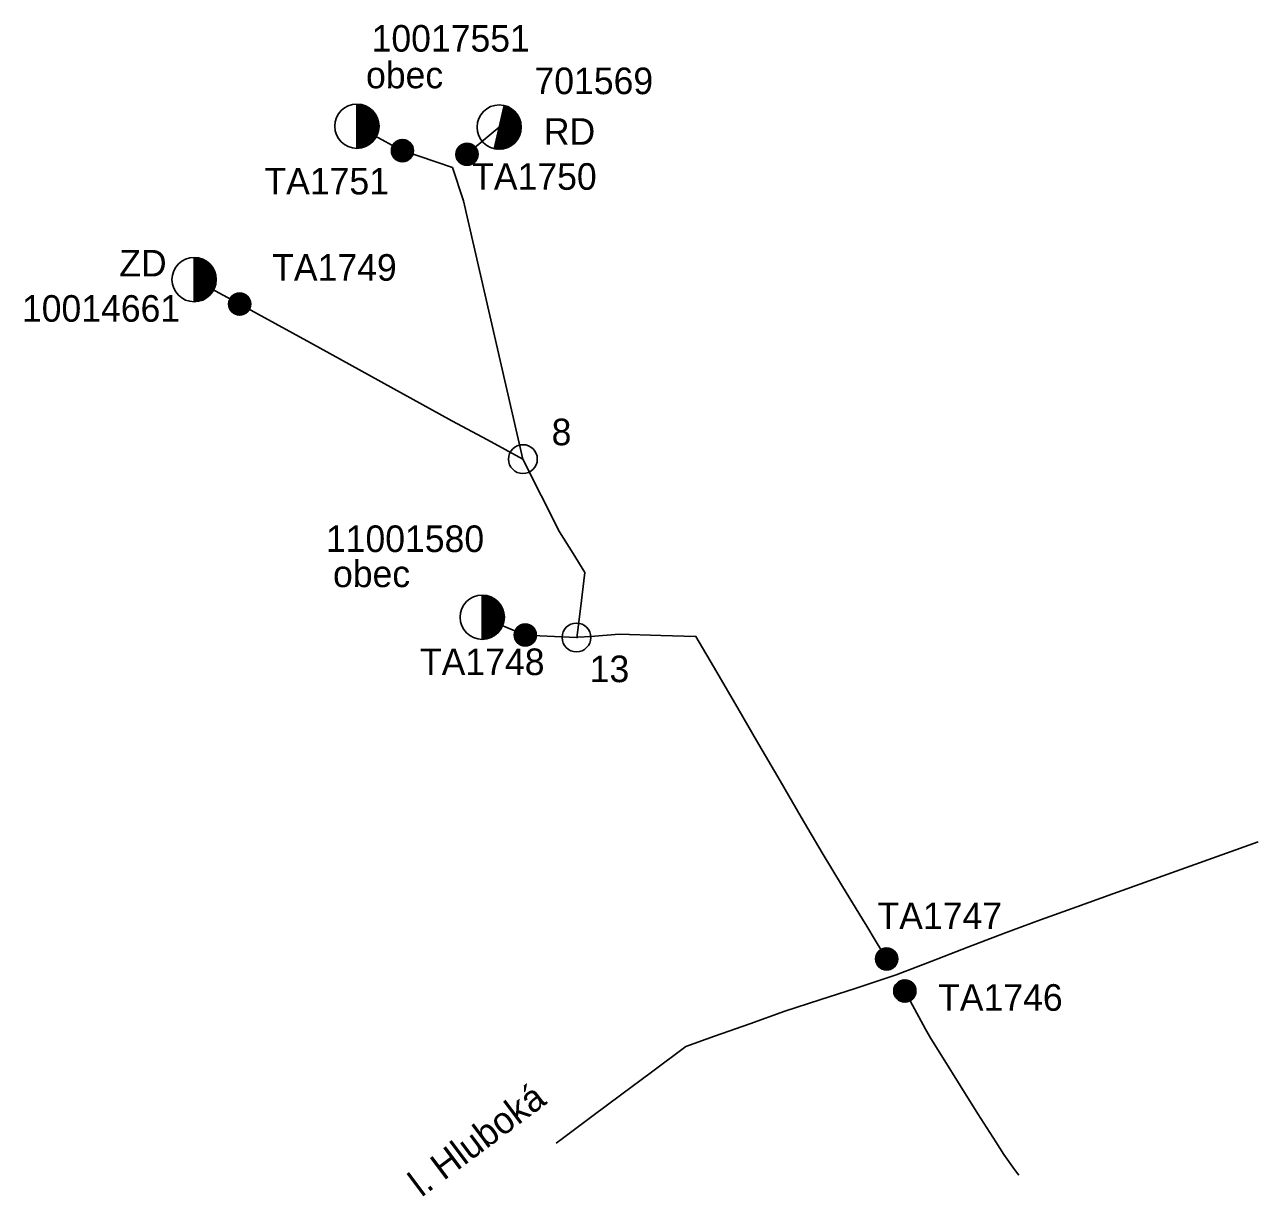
# Model space of a CAD drawing. Extents: x -749194 to -734612, y -1146817 to -1138558.
# Drawn here: x -741568 to -738789, y -1146738 to -1144095 of the extents above; entities that cross this region are included whole.
import ezdxf

# ---------------------------------------------------------------- set-up
doc = ezdxf.new("R2010")
doc.units = 0
for name, color, linetype in [('Default', 7, 'Continuous'), ('Vrstva 1', 7, 'Continuous'), ('Vrstva 2', 7, 'Continuous'), ('Vrstva 3', 7, 'Continuous'), ('Vrstva 5', 7, 'Continuous')]:
    doc.layers.add(name, color=color, linetype=linetype)

# ---------------------------------------------------------------- blocks, each defined once
blk = doc.blocks.new('PS440')
at = {"layer": 'Default'}
for p, q in [((-25, 0.1), (-0.1, 25)), ((-24.9, -1.2), (1.2, 24.9)), ((-24.9, 1.6), (-1.6, 24.9)), ((-24.8, -2.6), (2.6, 24.8)), ((-24.8, 3.2), (-3.2, 24.8)), ((-24.7, -3.8), (3.8, 24.7)), ((-24.5, -5), (5, 24.5)), ((-24.5, 4.9), (-4.9, 24.5)), ((-24.2, -6.2), (6.2, 24.2)), ((-24.1, 6.7), (-6.7, 24.1)), ((-23.9, -7.3), (7.3, 23.9)), ((-23.6, -8.3), (8.3, 23.6)), ((-23.4, 8.8), (-8.8, 23.4)), ((-23.2, -9.4), (9.4, 23.2)), ((-22.7, -10.3), (10.3, 22.7)), ((-22.3, -11.3), (11.3, 22.3)), ((-22.3, 11.3), (-11.3, 22.3)), ((-21.8, -12.2), (12.2, 21.8)), ((-21.3, -13.1), (13.1, 21.3)), ((-20.7, -14), (14, 20.7)), ((-20.1, -14.8), (14.8, 20.1)), ((-19.9, 15.2), (-15.2, 19.9)), ((-19.5, -15.6), (15.6, 19.5)), ((-18.9, -16.4), (16.4, 18.9)), ((-18.2, -17.1), (17.1, 18.2)), ((-17.5, -17.8), (17.8, 17.5)), ((-16.8, -18.5), (18.5, 16.8)), ((-16, -19.2), (19.2, 16)), ((-15.2, -19.8), (19.8, 15.2)), ((-14.4, -20.4), (20.4, 14.4)), ((-13.6, -21), (21, 13.6)), ((-12.7, -21.5), (21.5, 12.7)), ((-11.8, -22), (22, 11.8)), ((-10.8, -22.5), (22.5, 10.8)), ((-9.9, -22.9), (22.9, 9.9)), ((-8.9, -23.4), (23.4, 8.9)), ((-7.8, -23.7), (23.7, 7.8)), ((-6.7, -24.1), (24.1, 6.7)), ((-5.6, -24.3), (24.3, 5.6)), ((-4.4, -24.6), (24.6, 4.4)), ((-3.2, -24.8), (24.8, 3.2)), ((-1.9, -24.9), (24.9, 1.9)), ((-0.6, -25), (25, 0.6)), ((0.8, -25), (25, -0.8)), ((2.3, -24.9), (24.9, -2.3)), ((4, -24.7), (24.7, -4)), ((5.7, -24.3), (24.3, -5.7)), ((7.7, -23.8), (23.8, -7.7)), ((10, -22.9), (22.9, -10)), ((12.9, -21.4), (21.4, -12.9))]:
    blk.add_line(p, q, dxfattribs=at)
blk.add_circle((0, 0), 25, dxfattribs=at)
blk = doc.blocks.new('PS820')
at = {"layer": 'Vrstva 2'}
blk.add_circle((0, 0), 32.5, dxfattribs=at)
blk = doc.blocks.new('PS615')
at = {"layer": 'Default'}
for p, q in [((0, 49.1), (0.9, 50)), ((0, 46.3), (3.6, 49.9)), ((0, 47.7), (2.3, 49.9)), ((0, 44.8), (4.9, 49.8)), ((0, 43.4), (6.2, 49.6)), ((0, 42), (7.4, 49.4)), ((0, 40.6), (8.7, 49.2)), ((0, 39.2), (9.8, 49)), ((0, 37.8), (11, 48.8)), ((0, 36.4), (12.1, 48.5)), ((0, 34.9), (13.3, 48.2)), ((0, 33.5), (14.4, 47.9)), ((0, 32.1), (15.4, 47.6)), ((0, 30.7), (16.5, 47.2)), ((0, 29.3), (17.5, 46.8)), ((0, 27.9), (18.6, 46.4)), ((0, 26.5), (19.6, 46)), ((0, 25), (20.5, 45.6)), ((0, 23.6), (21.5, 45.1)), ((0, 22.2), (22.5, 44.7)), ((0, 20.8), (23.4, 44.2)), ((0, 19.4), (24.3, 43.7)), ((0, 18), (25.2, 43.2)), ((0, 16.6), (26.1, 42.6)), ((0, 15.1), (27, 42.1)), ((0, 13.7), (27.8, 41.5)), ((0, 12.3), (28.7, 41)), ((0, 10.9), (29.5, 40.4)), ((0, 9.5), (30.3, 39.8)), ((0, 8.1), (31.1, 39.2)), ((0, 6.7), (31.9, 38.5)), ((0, 5.2), (32.6, 37.9)), ((0, 3.8), (33.4, 37.2)), ((0, 2.4), (34.1, 36.5)), ((0, 1), (34.9, 35.9)), ((0, -0.4), (35.6, 35.1)), ((0, -1.8), (36.3, 34.4)), ((0, -3.2), (36.9, 33.7)), ((0, -4.7), (37.6, 32.9)), ((0, -6.1), (38.3, 32.2)), ((0, -7.5), (38.9, 31.4)), ((0, -8.9), (39.5, 30.6)), ((0, -10.3), (40.1, 29.8)), ((0, -11.7), (40.7, 29)), ((0, -13.1), (41.3, 28.2)), ((0, -14.6), (41.9, 27.3)), ((0, -16), (42.4, 26.5)), ((0, -17.4), (43, 25.6)), ((0, -18.8), (43.5, 24.7)), ((0, -20.2), (44, 23.8)), ((0, -21.6), (44.5, 22.8)), ((0, -23), (44.9, 21.9)), ((0, -24.5), (45.4, 20.9)), ((0, -25.9), (45.8, 20)), ((0, -27.3), (46.3, 19)), ((0, -28.7), (46.7, 18)), ((0, -30.1), (47, 16.9)), ((0, -31.5), (47.4, 15.9)), ((0, -32.9), (47.8, 14.8)), ((0, -34.4), (48.1, 13.7)), ((0, -35.8), (48.4, 12.6)), ((0, -37.2), (48.7, 11.5)), ((0, -38.6), (48.9, 10.3)), ((0, -40), (49.2, 9.1)), ((0, -41.4), (49.4, 7.9)), ((0, -42.8), (49.5, 6.7)), ((0, -44.3), (49.7, 5.4)), ((0, -45.7), (49.8, 4.2)), ((0, -47.1), (49.9, 2.8)), ((0, -48.5), (50, 1.5)), ((0, -49.9), (50, 0.1)), ((1.3, -50), (50, -1.3)), ((2.8, -49.9), (49.9, -2.8)), ((4.3, -49.8), (49.8, -4.3)), ((5.9, -49.6), (49.6, -5.9)), ((7.6, -49.4), (49.4, -7.6)), ((9.3, -49.1), (49.1, -9.3)), ((11.1, -48.8), (48.8, -11.1)), ((12.9, -48.3), (48.3, -12.9)), ((14.9, -47.7), (47.7, -14.9)), ((17.1, -47), (47, -17.1)), ((19.4, -46.1), (46.1, -19.4)), ((22, -44.9), (44.9, -22)), ((25, -43.3), (43.3, -25)), ((28.9, -40.8), (40.8, -28.9))]:
    blk.add_line(p, q, dxfattribs=at)
blk.add_lwpolyline([(0, 50), (0, -50)], dxfattribs=at)
blk.add_circle((0, 0), 50, dxfattribs=at)

msp = doc.modelspace()

# ---------------------------------------------------------------- linework, layer by layer
at = {"layer": 'Vrstva 1'}
for points in [[(-740715.4, -1144379.4), (-740715.7, -1144379.9), (-740784.4, -1144342.4), (-740818.2, -1144324.3)], [(-740569.8, -1144387.5), (-740497.2, -1144326.2)], [(-740602.6, -1144417.2), (-740715.4, -1144379.4)], [(-740443.6, -1145075.1), (-740577.8, -1144492.7), (-740602.6, -1144417.2)], [(-741082.7, -1144725.5), (-741082.7, -1144725.4), (-741129.6, -1144700.1), (-741169.8, -1144678.6), (-741185.4, -1144670.2)], [(-740443.6, -1145075.1), (-740443.6, -1145075.1), (-740523.9, -1145031.8), (-740603.8, -1144988.8), (-740763.3, -1144900.9), (-740922.9, -1144812.7), (-741002.3, -1144769), (-741082.7, -1144725.4), (-741082.7, -1144725.5)], [(-740323, -1145477.6), (-740322, -1145478.1), (-740313.9, -1145413.1), (-740303.8, -1145330.9), (-740330.5, -1145287.9), (-740360.8, -1145239.1), (-740443.6, -1145075.1)], [(-740535.4, -1145431.7), (-740438.4, -1145471.9)], [(-740438.4, -1145471.9), (-740323, -1145477.6)], [(-740323, -1145477.6), (-740321.7, -1145477.6), (-740320.6, -1145477.5), (-740319.9, -1145476.9), (-740290.7, -1145475.1), (-740226.8, -1145469.9), (-740132.7, -1145472.6), (-740053.3, -1145474.9), (-740006.4, -1145555.4), (-739956, -1145641.8), (-739916.5, -1145709.6), (-739863.4, -1145800.6), (-739815.7, -1145882.5), (-739768.5, -1145963.5), (-739722.4, -1146039.3), (-739677.4, -1146113), (-739667.8, -1146128.9), (-739648.9, -1146159.8), (-739646.6, -1146163.6), (-739623, -1146202.5)], [(-738784.9, -1145938), (-738866.7, -1145967.5), (-738948.6, -1145996.9), (-739030.5, -1146026.3), (-739112.5, -1146055.7), (-739194.2, -1146085.1), (-739275.7, -1146114.4), (-739357, -1146144.5), (-739439.5, -1146176.3), (-739521.3, -1146207.8), (-739601.1, -1146238.6)], [(-740368.4, -1146617.9), (-740354.6, -1146607.6), (-740288.1, -1146557.9), (-740220.8, -1146507.7), (-740153.7, -1146457.6), (-740076.1, -1146399.7), (-740011, -1146376.6), (-739931.9, -1146348.6), (-739852.5, -1146320.4), (-739774, -1146294.8), (-739694.1, -1146268.8), (-739601.1, -1146238.6)], [(-739324.9, -1146690.2), (-739334.2, -1146677.1), (-739358.4, -1146643.3), (-739376.5, -1146615.1), (-739417, -1146551.7), (-739456.8, -1146488.3), (-739495.7, -1146426.2), (-739523.3, -1146382.3), (-739535, -1146360.6), (-739569.7, -1146296.6), (-739581.9, -1146274.7), (-739570.5, -1146295)]]:
    msp.add_lwpolyline(points, dxfattribs=at)

# ---------------------------------------------------------------- block references
at = {"layer": 'Vrstva 2'}
for p, rotation in [((-740715.4, -1144379.4), -36.34745823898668), ((-740569.8, -1144387.5), 66.8839611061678), ((-741082.7, -1144725.5), -28.446830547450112), ((-740438.4, -1145471.9), 0.7679332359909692), ((-739623, -1146202.5), 121.2413667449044), ((-739581.9, -1146274.7), -62.780838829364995)]:
    msp.add_blockref('PS440', p, dxfattribs=dict(at, rotation=rotation))
at = {"layer": 'Vrstva 3', "rotation": -12.66228615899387}
msp.add_blockref('PS615', (-740497.2, -1144326.2), dxfattribs=at)
at = {"layer": 'Vrstva 3'}
for p in [(-740818.2, -1144324.3), (-741185.4, -1144670.2), (-740535.4, -1145431.7)]:
    msp.add_blockref('PS615', p, dxfattribs=at)
at = {"layer": 'Vrstva 5'}
for p, rotation in [((-740443.6, -1145075.1), -30.61136111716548), ((-740322.8, -1145477.4), 0.7679332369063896)]:
    msp.add_blockref('PS820', p, dxfattribs=dict(at, rotation=rotation))

# ---------------------------------------------------------------- texts
at = {"layer": 'Vrstva 1'}
msp.add_text('l. Hluboká', height=60, rotation=36.846, dxfattribs=at).set_placement((-740672.6, -1146741.2))
at = {"layer": 'Vrstva 2'}
for s, p in [('TA1750', (-740558.2, -1144467.7)), ('TA1751', (-741026.9, -1144478.2)), ('TA1749', (-741009.4, -1144672.8)), ('TA1748', (-740675.9, -1145562.3)), ('TA1747', (-739643.6, -1146135.3)), ('TA1746', (-739506.8, -1146319.4))]:
    msp.add_text(s, height=60, dxfattribs=at).set_placement(p)
at = {"layer": 'Vrstva 3'}
for s, p in [('10017551', (-740785, -1144156.1)), ('obec', (-740797.6, -1144238.7)), ('701569', (-740417.5, -1144252)), ('RD', (-740396.3, -1144366.2)), ('ZD', (-741354.4, -1144663.2)), ('10014661', (-741574, -1144765.3)), ('11001580', (-740888.1, -1145284.7)), ('obec', (-740872.1, -1145363.9))]:
    msp.add_text(s, height=60, dxfattribs=at).set_placement(p)
at = {"layer": 'Vrstva 5'}
for s, p in [('8', (-740378.9, -1145043.9)), ('13', (-740292.9, -1145578.2))]:
    msp.add_text(s, height=60, dxfattribs=at).set_placement(p)

doc.saveas('drawing.dxf')
